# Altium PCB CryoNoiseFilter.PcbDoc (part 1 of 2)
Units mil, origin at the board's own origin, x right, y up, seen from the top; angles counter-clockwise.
Board outline 2990 x 2110 mil, 2 copper layers (Top Layer, Bottom Layer); 246 components, 223 nets, 580 pads, 66 vias.
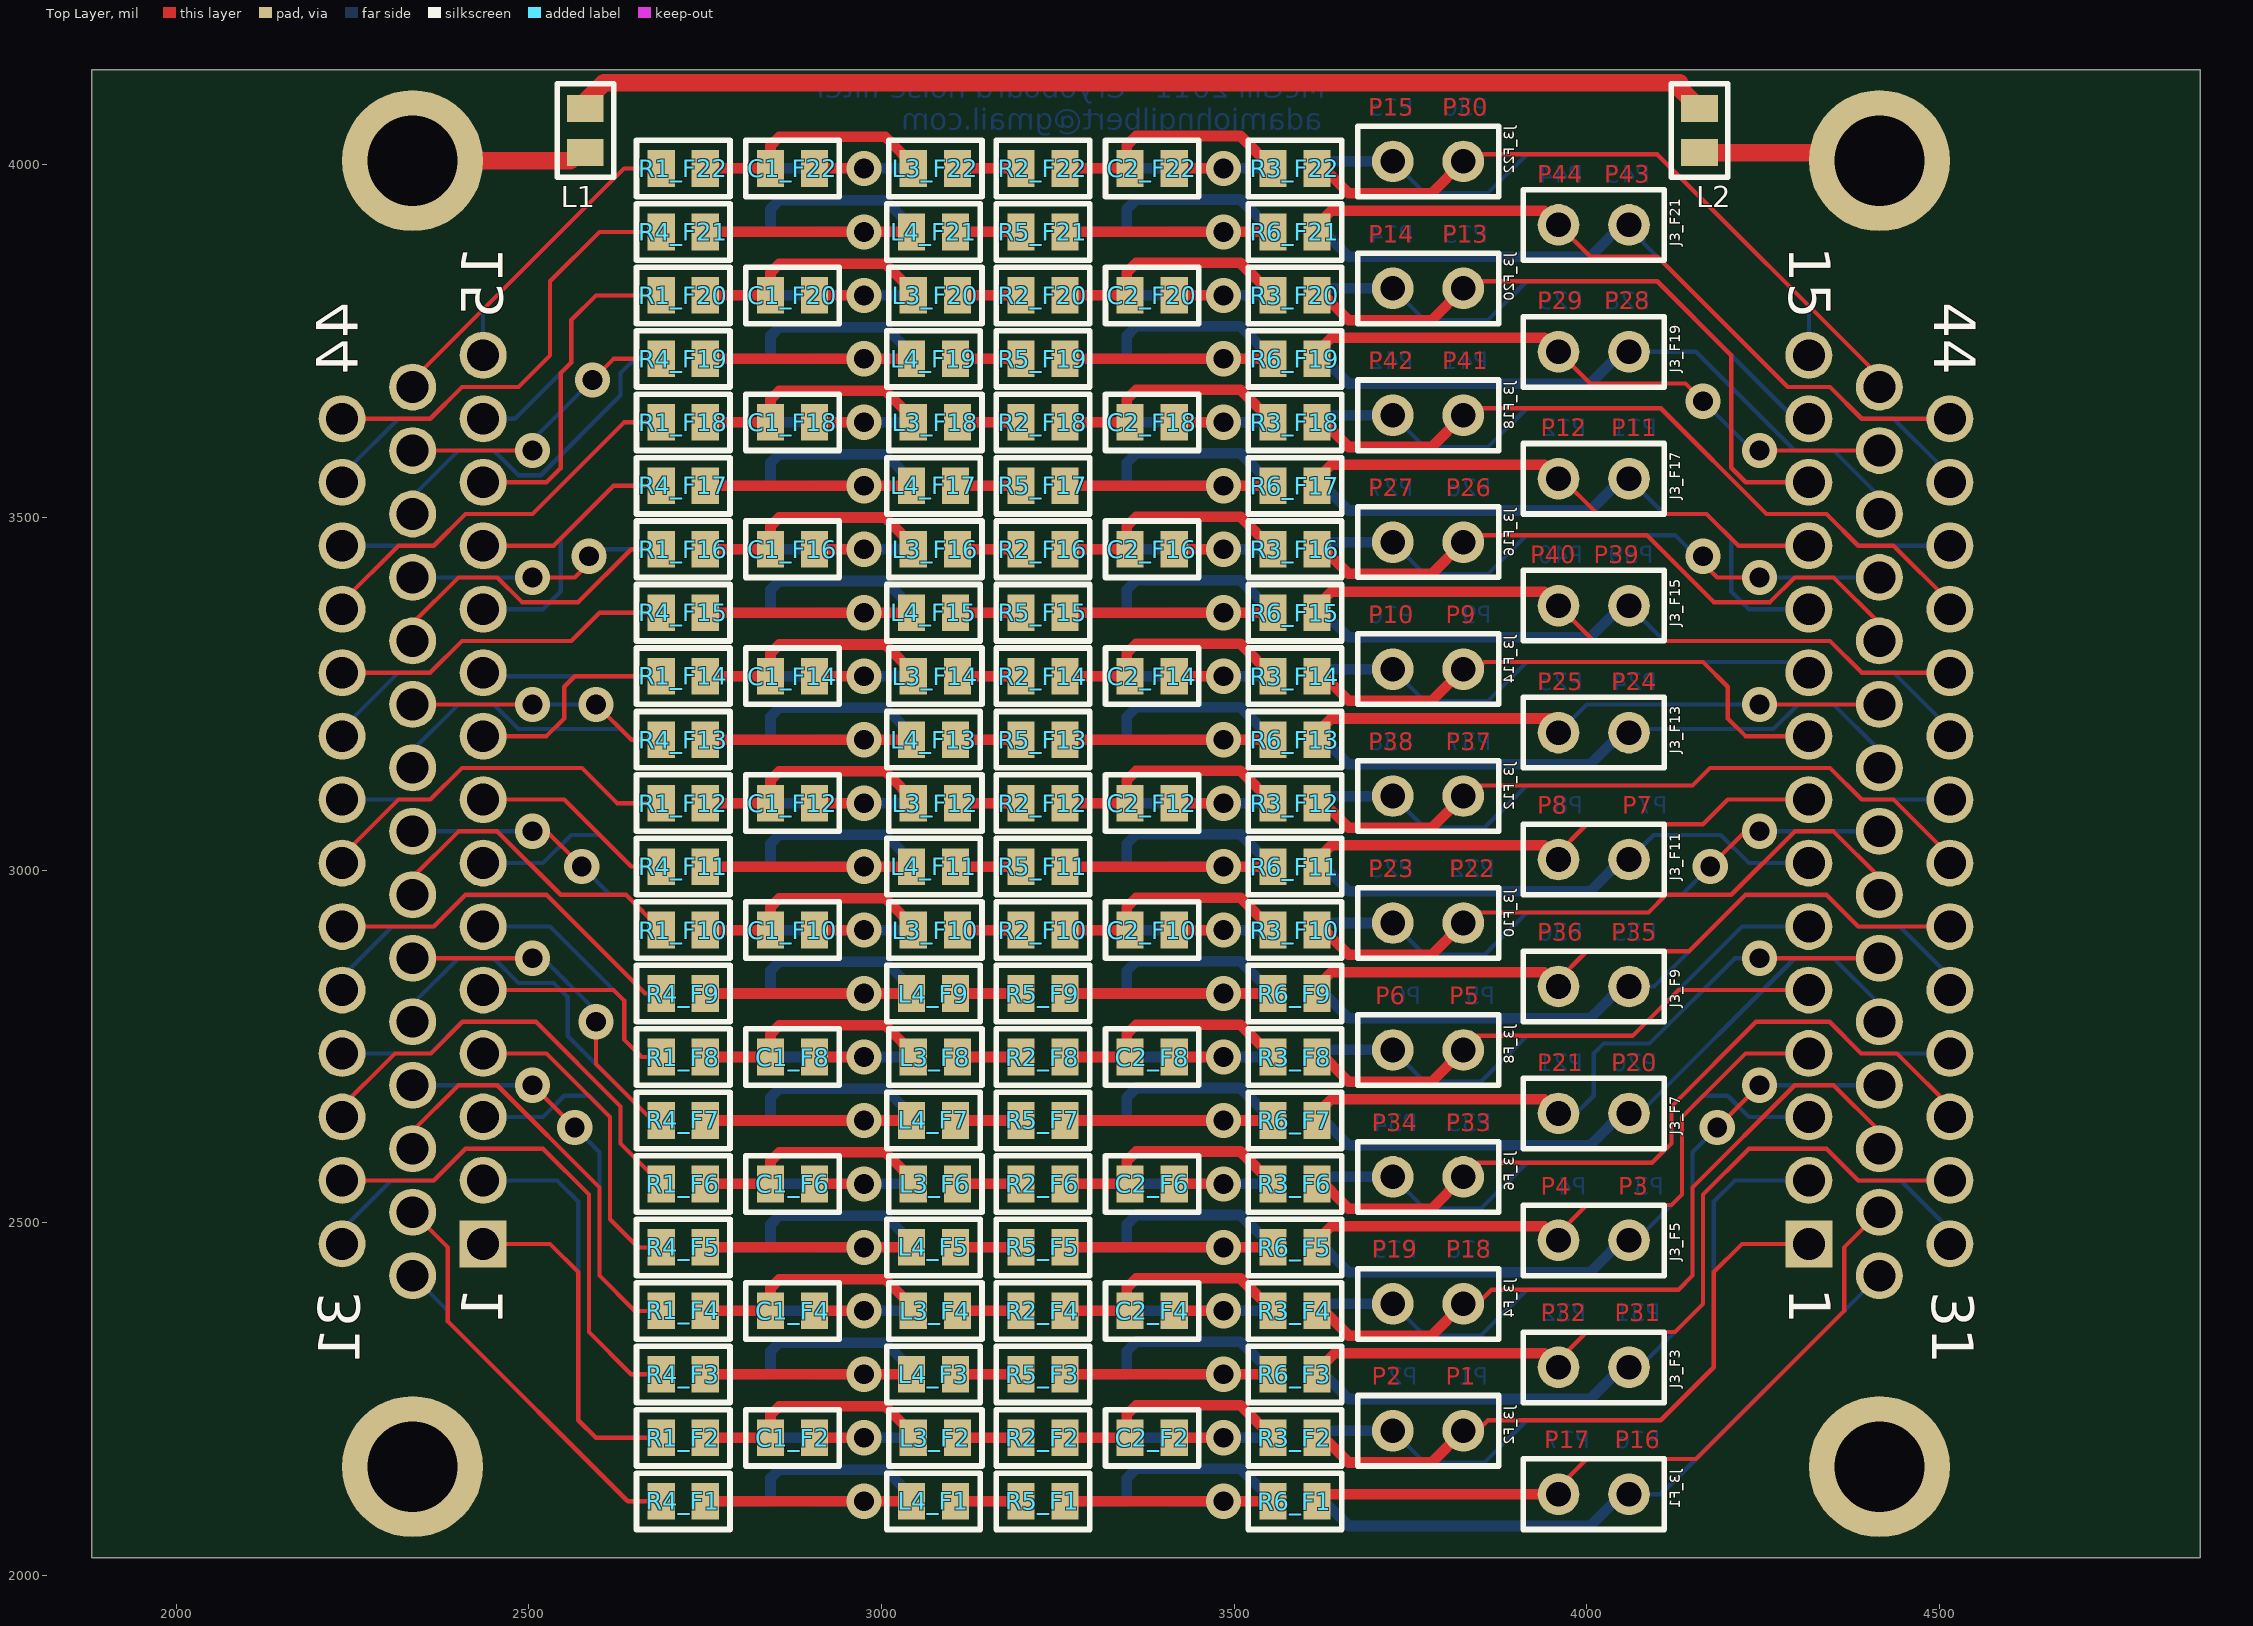
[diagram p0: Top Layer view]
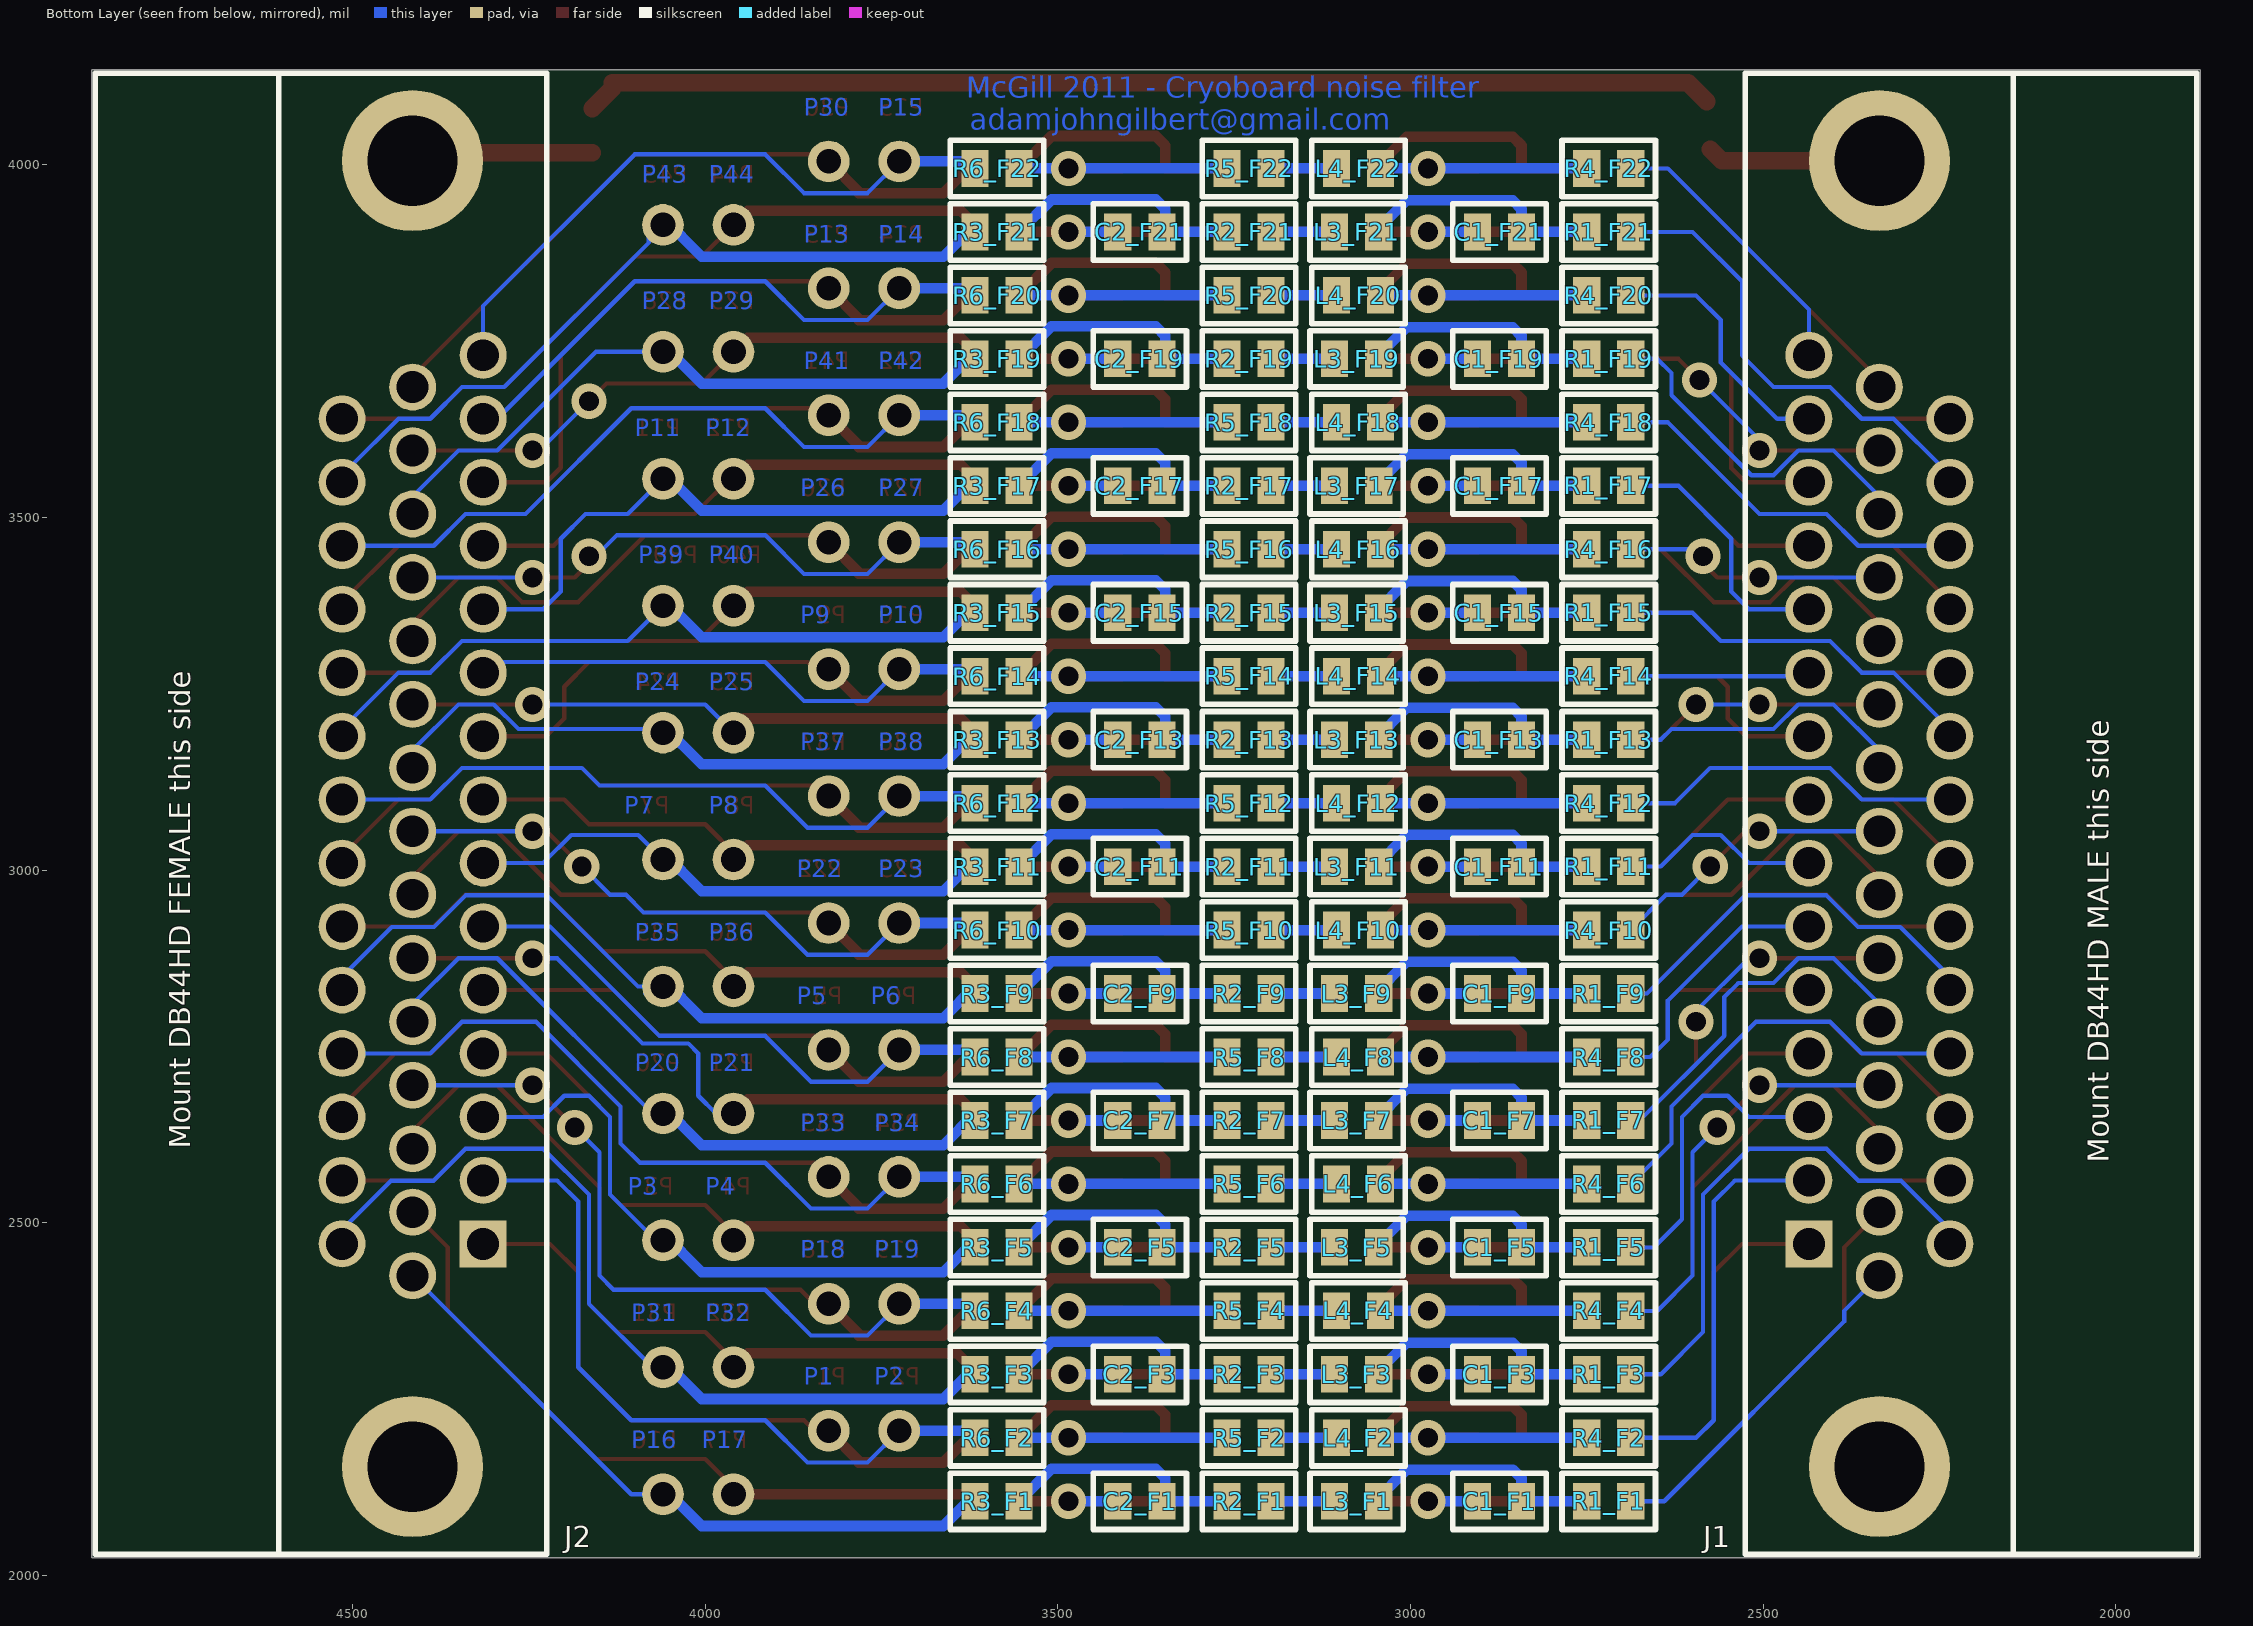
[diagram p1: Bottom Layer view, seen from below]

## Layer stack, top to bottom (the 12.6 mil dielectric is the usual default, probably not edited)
Top Layer: signal copper 1.4
Dielectric: dielectric 12.6, FR-4, Dk 4.8
Bottom Layer: signal copper 1.4

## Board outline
1885,4135 4870,4135 4870,2025 1880,2025 1880,4135

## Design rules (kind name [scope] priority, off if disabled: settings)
Clearance [All] p1: gap=5
ComponentClearance [All] p1: gap=2 collisioncheckmode=3 verticalgap=10 showdistances=FALSE
HoleToHoleClearance [All] p1: gap=5 allowstackedmicrovias=TRUE
MinimumSolderMaskSliver [All] p1: minsoldermaskwidth=0
PolygonConnect [All] p1: connectstyle=Relief reliefconductorwidth=10 reliefentries=4 polygonreliefangle="90 Angle"
RoomDefinition F21 [InComponentClass('F21')] p1: confinementstyle=ConfineIn formatcopy=TRUE lockcomponents=FALSE outline 2612.5,3860 4125,3860 4125,3970 2612.5,3970
RoomDefinition F19 [InComponentClass('F19')] p2: confinementstyle=ConfineIn formatcopy=TRUE lockcomponents=FALSE outline 2612.5,3680 4125,3680 4125,3790 2612.5,3790
RoomDefinition F17 [InComponentClass('F17')] p3: confinementstyle=ConfineIn formatcopy=TRUE lockcomponents=FALSE outline 2612.5,3500 4125,3500 4125,3610 2612.5,3610
RoomDefinition F15 [InComponentClass('F15')] p4: confinementstyle=ConfineIn formatcopy=TRUE lockcomponents=FALSE outline 2612.5,3320 4125,3320 4125,3430 2612.5,3430
RoomDefinition F13 [InComponentClass('F13')] p5: confinementstyle=ConfineIn formatcopy=TRUE lockcomponents=FALSE outline 2612.5,3140 4125,3140 4125,3250 2612.5,3250
RoomDefinition F11 [InComponentClass('F11')] p6: confinementstyle=ConfineIn formatcopy=TRUE lockcomponents=FALSE outline 2612.5,2960 4125,2960 4125,3070 2612.5,3070
RoomDefinition F9 [InComponentClass('F9')] p7: confinementstyle=ConfineIn formatcopy=TRUE lockcomponents=FALSE outline 2612.5,2780 4125,2780 4125,2890 2612.5,2890
RoomDefinition F7 [InComponentClass('F7')] p8: confinementstyle=ConfineIn formatcopy=TRUE lockcomponents=FALSE outline 2612.5,2600 4125,2600 4125,2710 2612.5,2710
RoomDefinition F5 [InComponentClass('F5')] p9: confinementstyle=ConfineIn formatcopy=TRUE lockcomponents=FALSE outline 2612.5,2420 4125,2420 4125,2530 2612.5,2530
RoomDefinition F3 [InComponentClass('F3')] p10: confinementstyle=ConfineIn formatcopy=TRUE lockcomponents=FALSE outline 2612.5,2240 4125,2240 4125,2350 2612.5,2350
RoomDefinition F22 [InComponentClass('F22')] p11: confinementstyle=ConfineIn formatcopy=FALSE lockcomponents=FALSE outline 2612.5,3950 3912.5,3950 3912.5,4060 2612.5,4060
RoomDefinition F20 [InComponentClass('F20')] p12: confinementstyle=ConfineIn formatcopy=FALSE lockcomponents=FALSE outline 2612.5,3770 3912.5,3770 3912.5,3880 2612.5,3880
RoomDefinition F18 [InComponentClass('F18')] p13: confinementstyle=ConfineIn formatcopy=FALSE lockcomponents=FALSE outline 2612.5,3590 3912.5,3590 3912.5,3700 2612.5,3700
RoomDefinition F16 [InComponentClass('F16')] p14: confinementstyle=ConfineIn formatcopy=FALSE lockcomponents=FALSE outline 2612.5,3410 3912.5,3410 3912.5,3520 2612.5,3520
RoomDefinition F14 [InComponentClass('F14')] p15: confinementstyle=ConfineIn formatcopy=FALSE lockcomponents=FALSE outline 2612.5,3230 3912.5,3230 3912.5,3340 2612.5,3340
RoomDefinition F12 [InComponentClass('F12')] p16: confinementstyle=ConfineIn formatcopy=FALSE lockcomponents=FALSE outline 2612.5,3050 3912.5,3050 3912.5,3160 2612.5,3160
RoomDefinition F10 [InComponentClass('F10')] p17: confinementstyle=ConfineIn formatcopy=FALSE lockcomponents=FALSE outline 2612.5,2870 3912.5,2870 3912.5,2980 2612.5,2980
RoomDefinition F8 [InComponentClass('F8')] p18: confinementstyle=ConfineIn formatcopy=FALSE lockcomponents=FALSE outline 2612.5,2690 3912.5,2690 3912.5,2800 2612.5,2800
RoomDefinition F6 [InComponentClass('F6')] p19: confinementstyle=ConfineIn formatcopy=FALSE lockcomponents=FALSE outline 2612.5,2510 3912.5,2510 3912.5,2620 2612.5,2620
RoomDefinition F4 [InComponentClass('F4')] p20: confinementstyle=ConfineIn formatcopy=FALSE lockcomponents=FALSE outline 2612.5,2330 3912.5,2330 3912.5,2440 2612.5,2440
RoomDefinition F2 [InComponentClass('F2')] p21: confinementstyle=ConfineIn formatcopy=FALSE lockcomponents=FALSE outline 2612.5,2150 3912.5,2150 3912.5,2260 2612.5,2260
RoomDefinition F1 [InComponentClass('F1')] p22: confinementstyle=ConfineIn formatcopy=TRUE lockcomponents=FALSE outline 2612.5,2060 4125,2060 4125,2170 2612.5,2170
RoutingVias [All] p1: holewidth=28 width=50 viastyle="Through Hole" minholewidth=28 minwidth=50 maxholewidth=28 maxwidth=50
SilkToSilkClearance [All] p1: silktosilkclearance=0
SilkscreenOverComponentPads [All] p1: minsilkscreentomaskgap=0
SolderMaskExpansion [All] p1: expansion=4
Width [All] p1: maxlimit=100 minlimit=6 preferedwidth=15
23 further rules are at their usual default settings.

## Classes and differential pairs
channel class LCFilter: F1 F2 F3 F4 F5 F6 F7 F8 F9 F10 F11 F12 F13 F14 F15 F16 F17 F18 F19 F20 F21 F22
net class OUTP[1..22]: OUTP1 OUTP2 OUTP3 OUTP4 OUTP5 OUTP6 OUTP7 OUTP8 OUTP9 OUTP10 OUTP11 OUTP12 OUTP13 OUTP14 OUTP15 OUTP16 OUTP17 OUTP18 OUTP19 OUTP20 OUTP21 OUTP22
net class OUTN[1..22]: OUTN1 OUTN2 OUTN3 OUTN4 OUTN5 OUTN6 OUTN7 OUTN8 OUTN9 OUTN10 OUTN11 OUTN12 OUTN13 OUTN14 OUTN15 OUTN16 OUTN17 OUTN18 OUTN19 OUTN20 OUTN21 OUTN22
net class INP[1..22]: INP1 INP2 INP3 INP4 INP5 INP6 INP7 INP8 INP9 INP10 INP11 INP12 INP13 INP14 INP15 INP16 INP17 INP18 INP19 INP20 INP21 INP22
net class INN[1..22]: INN1 INN2 INN3 INN4 INN5 INN6 INN7 INN8 INN9 INN10 INN11 INN12 INN13 INN14 INN15 INN16 INN17 INN18 INN19 INN20 INN21 INN22
component class F22: C1_F22 C2_F22 J3_F22 L3_F22 L4_F22 R1_F22 R2_F22 R3_F22 R4_F22 R5_F22 R6_F22
component class F21: C1_F21 C2_F21 J3_F21 L3_F21 L4_F21 R1_F21 R2_F21 R3_F21 R4_F21 R5_F21 R6_F21
component class F20: C1_F20 C2_F20 J3_F20 L3_F20 L4_F20 R1_F20 R2_F20 R3_F20 R4_F20 R5_F20 R6_F20
component class F19: C1_F19 C2_F19 J3_F19 L3_F19 L4_F19 R1_F19 R2_F19 R3_F19 R4_F19 R5_F19 R6_F19
component class F18: C1_F18 C2_F18 J3_F18 L3_F18 L4_F18 R1_F18 R2_F18 R3_F18 R4_F18 R5_F18 R6_F18
component class F17: C1_F17 C2_F17 J3_F17 L3_F17 L4_F17 R1_F17 R2_F17 R3_F17 R4_F17 R5_F17 R6_F17
component class F16: C1_F16 C2_F16 J3_F16 L3_F16 L4_F16 R1_F16 R2_F16 R3_F16 R4_F16 R5_F16 R6_F16
component class F15: C1_F15 C2_F15 J3_F15 L3_F15 L4_F15 R1_F15 R2_F15 R3_F15 R4_F15 R5_F15 R6_F15
component class F14: C1_F14 C2_F14 J3_F14 L3_F14 L4_F14 R1_F14 R2_F14 R3_F14 R4_F14 R5_F14 R6_F14
component class F13: C1_F13 C2_F13 J3_F13 L3_F13 L4_F13 R1_F13 R2_F13 R3_F13 R4_F13 R5_F13 R6_F13
component class F12: C1_F12 C2_F12 J3_F12 L3_F12 L4_F12 R1_F12 R2_F12 R3_F12 R4_F12 R5_F12 R6_F12
component class F11: C1_F11 C2_F11 J3_F11 L3_F11 L4_F11 R1_F11 R2_F11 R3_F11 R4_F11 R5_F11 R6_F11
component class F10: C1_F10 C2_F10 J3_F10 L3_F10 L4_F10 R1_F10 R2_F10 R3_F10 R4_F10 R5_F10 R6_F10
component class F9: C1_F9 C2_F9 J3_F9 L3_F9 L4_F9 R1_F9 R2_F9 R3_F9 R4_F9 R5_F9 R6_F9
component class F8: C1_F8 C2_F8 J3_F8 L3_F8 L4_F8 R1_F8 R2_F8 R3_F8 R4_F8 R5_F8 R6_F8
component class F7: C1_F7 C2_F7 J3_F7 L3_F7 L4_F7 R1_F7 R2_F7 R3_F7 R4_F7 R5_F7 R6_F7
component class F6: C1_F6 C2_F6 J3_F6 L3_F6 L4_F6 R1_F6 R2_F6 R3_F6 R4_F6 R5_F6 R6_F6
component class F5: C1_F5 C2_F5 J3_F5 L3_F5 L4_F5 R1_F5 R2_F5 R3_F5 R4_F5 R5_F5 R6_F5
component class F4: C1_F4 C2_F4 J3_F4 L3_F4 L4_F4 R1_F4 R2_F4 R3_F4 R4_F4 R5_F4 R6_F4
component class F3: C1_F3 C2_F3 J3_F3 L3_F3 L4_F3 R1_F3 R2_F3 R3_F3 R4_F3 R5_F3 R6_F3
component class F2: C1_F2 C2_F2 J3_F2 L3_F2 L4_F2 R1_F2 R2_F2 R3_F2 R4_F2 R5_F2 R6_F2
component class F1: C1_F1 C2_F1 J3_F1 L3_F1 L4_F1 R1_F1 R2_F1 R3_F1 R4_F1 R5_F1 R6_F1
component class CryoNoiseFilter: J1 J2 L1

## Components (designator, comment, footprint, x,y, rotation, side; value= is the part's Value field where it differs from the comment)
C1_F1 "0.1uF" 0805 2905,2105 r180 bottom (schematic designator C1)
C1_F2 "0.1uF" 0805 2905,2195 r180 top (schematic designator C1)
C1_F3 "0.1uF" 0805 2905,2285 r180 bottom (schematic designator C1)
C1_F4 "0.1uF" 0805 2905,2375 r180 top (schematic designator C1)
C1_F5 "0.1uF" 0805 2905,2465 r180 bottom (schematic designator C1)
C1_F6 "0.1uF" 0805 2905,2555 r180 top (schematic designator C1)
C1_F7 "0.1uF" 0805 2905,2645 r180 bottom (schematic designator C1)
C1_F8 "0.1uF" 0805 2905,2735 r180 top (schematic designator C1)
C1_F9 "0.1uF" 0805 2905,2825 r180 bottom (schematic designator C1)
C1_F10 "0.1uF" 0805 2905,2915 r180 top (schematic designator C1)
C1_F11 "0.1uF" 0805 2905,3005 r180 bottom (schematic designator C1)
C1_F12 "0.1uF" 0805 2905,3095 r180 top (schematic designator C1)
C1_F13 "0.1uF" 0805 2905,3185 r180 bottom (schematic designator C1)
C1_F14 "0.1uF" 0805 2905,3275 r180 top (schematic designator C1)
C1_F15 "0.1uF" 0805 2905,3365 r180 bottom (schematic designator C1)
C1_F16 "0.1uF" 0805 2905,3455 r180 top (schematic designator C1)
C1_F17 "0.1uF" 0805 2905,3545 r180 bottom (schematic designator C1)
C1_F18 "0.1uF" 0805 2905,3635 r180 top (schematic designator C1)
C1_F19 "0.1uF" 0805 2905,3725 r180 bottom (schematic designator C1)
C1_F20 "0.1uF" 0805 2905,3815 r180 top (schematic designator C1)
C1_F21 "0.1uF" 0805 2905,3905 r180 bottom (schematic designator C1)
C1_F22 "0.1uF" 0805 2905,3995 r180 top (schematic designator C1)
C2_F1 "0.1uF" 0805 3415,2105 r180 bottom (schematic designator C2)
C2_F2 "0.1uF" 0805 3415,2195 r180 top (schematic designator C2)
C2_F3 "0.1uF" 0805 3415,2285 r180 bottom (schematic designator C2)
C2_F4 "0.1uF" 0805 3415,2375 r180 top (schematic designator C2)
C2_F5 "0.1uF" 0805 3415,2465 r180 bottom (schematic designator C2)
C2_F6 "0.1uF" 0805 3415,2555 r180 top (schematic designator C2)
C2_F7 "0.1uF" 0805 3415,2645 r180 bottom (schematic designator C2)
C2_F8 "0.1uF" 0805 3415,2735 r180 top (schematic designator C2)
C2_F9 "0.1uF" 0805 3415,2825 r180 bottom (schematic designator C2)
C2_F10 "0.1uF" 0805 3415,2915 r180 top (schematic designator C2)
C2_F11 "0.1uF" 0805 3415,3005 r180 bottom (schematic designator C2)
C2_F12 "0.1uF" 0805 3415,3095 r180 top (schematic designator C2)
C2_F13 "0.1uF" 0805 3415,3185 r180 bottom (schematic designator C2)
C2_F14 "0.1uF" 0805 3415,3275 r180 top (schematic designator C2)
C2_F15 "0.1uF" 0805 3415,3365 r180 bottom (schematic designator C2)
C2_F16 "0.1uF" 0805 3415,3455 r180 top (schematic designator C2)
C2_F17 "0.1uF" 0805 3415,3545 r180 bottom (schematic designator C2)
C2_F18 "0.1uF" 0805 3415,3635 r180 top (schematic designator C2)
C2_F19 "0.1uF" 0805 3415,3725 r180 bottom (schematic designator C2)
C2_F20 "0.1uF" 0805 3415,3815 r180 top (schematic designator C2)
C2_F21 "0.1uF" 0805 3415,3905 r180 bottom (schematic designator C2)
C2_F22 "0.1uF" 0805 3415,3995 r180 top (schematic designator C2)
J1 "HDDB44-F, 5748482-5" DSUBHD44#1 2435,2470 r90 bottom
J2 "HDDB44-F, 5748482-5" DSUBHD44#2 4315,2470 r90 bottom
J3_F1 "Header 2pin 0.1\"" HDR1X2 4060,2115 r180 top (schematic designator J3)
J3_F2 "Header 2pin 0.1\"" HDR1X2 3825,2205 r180 top (schematic designator J3)
J3_F3 "Header 2pin 0.1\"" HDR1X2 4060,2295 r180 top (schematic designator J3)
J3_F4 "Header 2pin 0.1\"" HDR1X2 3825,2385 r180 top (schematic designator J3)
J3_F5 "Header 2pin 0.1\"" HDR1X2 4060,2475 r180 top (schematic designator J3)
J3_F6 "Header 2pin 0.1\"" HDR1X2 3825,2565 r180 top (schematic designator J3)
J3_F7 "Header 2pin 0.1\"" HDR1X2 4060,2655 r180 top (schematic designator J3)
J3_F8 "Header 2pin 0.1\"" HDR1X2 3825,2745 r180 top (schematic designator J3)
J3_F9 "Header 2pin 0.1\"" HDR1X2 4060,2835 r180 top (schematic designator J3)
J3_F10 "Header 2pin 0.1\"" HDR1X2 3825,2925 r180 top (schematic designator J3)
J3_F11 "Header 2pin 0.1\"" HDR1X2 4060,3015 r180 top (schematic designator J3)
J3_F12 "Header 2pin 0.1\"" HDR1X2 3825,3105 r180 top (schematic designator J3)
J3_F13 "Header 2pin 0.1\"" HDR1X2 4060,3195 r180 top (schematic designator J3)
J3_F14 "Header 2pin 0.1\"" HDR1X2 3825,3285 r180 top (schematic designator J3)
J3_F15 "Header 2pin 0.1\"" HDR1X2 4060,3375 r180 top (schematic designator J3)
J3_F16 "Header 2pin 0.1\"" HDR1X2 3825,3465 r180 top (schematic designator J3)
J3_F17 "Header 2pin 0.1\"" HDR1X2 4060,3555 r180 top (schematic designator J3)
J3_F18 "Header 2pin 0.1\"" HDR1X2 3825,3645 r180 top (schematic designator J3)
J3_F19 "Header 2pin 0.1\"" HDR1X2 4060,3735 r180 top (schematic designator J3)
J3_F20 "Header 2pin 0.1\"" HDR1X2 3825,3825 r180 top (schematic designator J3)
J3_F21 "Header 2pin 0.1\"" HDR1X2 4060,3915 r180 top (schematic designator J3)
J3_F22 "Header 2pin 0.1\"" HDR1X2 3825,4005 r180 top (schematic designator J3)
L1 "10uH" 0805 2580,4080 r270 top
L2 "10uH" 0805 4160,4080 r270 top
L3_F1 "10uH" 0805 3045,2105 r0 bottom (schematic designator L3)
L3_F2 "10uH" 0805 3045,2195 r0 top (schematic designator L3)
L3_F3 "10uH" 0805 3045,2285 r0 bottom (schematic designator L3)
L3_F4 "10uH" 0805 3045,2375 r0 top (schematic designator L3)
L3_F5 "10uH" 0805 3045,2465 r0 bottom (schematic designator L3)
L3_F6 "10uH" 0805 3045,2555 r0 top (schematic designator L3)
L3_F7 "10uH" 0805 3045,2645 r0 bottom (schematic designator L3)
L3_F8 "10uH" 0805 3045,2735 r0 top (schematic designator L3)
L3_F9 "10uH" 0805 3045,2825 r0 bottom (schematic designator L3)
L3_F10 "10uH" 0805 3045,2915 r0 top (schematic designator L3)
L3_F11 "10uH" 0805 3045,3005 r0 bottom (schematic designator L3)
L3_F12 "10uH" 0805 3045,3095 r0 top (schematic designator L3)
L3_F13 "10uH" 0805 3045,3185 r0 bottom (schematic designator L3)
L3_F14 "10uH" 0805 3045,3275 r0 top (schematic designator L3)
L3_F15 "10uH" 0805 3045,3365 r0 bottom (schematic designator L3)
L3_F16 "10uH" 0805 3045,3455 r0 top (schematic designator L3)
L3_F17 "10uH" 0805 3045,3545 r0 bottom (schematic designator L3)
L3_F18 "10uH" 0805 3045,3635 r0 top (schematic designator L3)
L3_F19 "10uH" 0805 3045,3725 r0 bottom (schematic designator L3)
L3_F20 "10uH" 0805 3045,3815 r0 top (schematic designator L3)
L3_F21 "10uH" 0805 3045,3905 r0 bottom (schematic designator L3)
L3_F22 "10uH" 0805 3045,3995 r0 top (schematic designator L3)
L4_F1 "10uH" 0805 3042.5,2105 r0 top (schematic designator L4)
L4_F2 "10uH" 0805 3042.5,2195 r0 bottom (schematic designator L4)
L4_F3 "10uH" 0805 3042.5,2285 r0 top (schematic designator L4)
L4_F4 "10uH" 0805 3042.5,2375 r0 bottom (schematic designator L4)
L4_F5 "10uH" 0805 3042.5,2465 r0 top (schematic designator L4)
L4_F6 "10uH" 0805 3042.5,2555 r0 bottom (schematic designator L4)
L4_F7 "10uH" 0805 3042.5,2645 r0 top (schematic designator L4)
L4_F8 "10uH" 0805 3042.5,2735 r0 bottom (schematic designator L4)
L4_F9 "10uH" 0805 3042.5,2825 r0 top (schematic designator L4)
L4_F10 "10uH" 0805 3042.5,2915 r0 bottom (schematic designator L4)
L4_F11 "10uH" 0805 3042.5,3005 r0 top (schematic designator L4)
L4_F12 "10uH" 0805 3042.5,3095 r0 bottom (schematic designator L4)
L4_F13 "10uH" 0805 3042.5,3185 r0 top (schematic designator L4)
L4_F14 "10uH" 0805 3042.5,3275 r0 bottom (schematic designator L4)
L4_F15 "10uH" 0805 3042.5,3365 r0 top (schematic designator L4)
L4_F16 "10uH" 0805 3042.5,3455 r0 bottom (schematic designator L4)
L4_F17 "10uH" 0805 3042.5,3545 r0 top (schematic designator L4)
L4_F18 "10uH" 0805 3042.5,3635 r0 bottom (schematic designator L4)
L4_F19 "10uH" 0805 3042.5,3725 r0 top (schematic designator L4)
L4_F20 "10uH" 0805 3042.5,3815 r0 bottom (schematic designator L4)
L4_F21 "10uH" 0805 3042.5,3905 r0 top (schematic designator L4)
L4_F22 "10uH" 0805 3042.5,3995 r0 bottom (schematic designator L4)
R1_F1 "0805" 0805 2687.5,2105 r0 bottom (schematic designator R1)
R1_F2 "0805" 0805 2687.5,2195 r0 top (schematic designator R1)
R1_F3 "0805" 0805 2687.5,2285 r0 bottom (schematic designator R1)
R1_F4 "0805" 0805 2687.5,2375 r0 top (schematic designator R1)
R1_F5 "0805" 0805 2687.5,2465 r0 bottom (schematic designator R1)
R1_F6 "0805" 0805 2687.5,2555 r0 top (schematic designator R1)
R1_F7 "0805" 0805 2687.5,2645 r0 bottom (schematic designator R1)
R1_F8 "0805" 0805 2687.5,2735 r0 top (schematic designator R1)
R1_F9 "0805" 0805 2687.5,2825 r0 bottom (schematic designator R1)
R1_F10 "0805" 0805 2687.5,2915 r0 top (schematic designator R1)
R1_F11 "0805" 0805 2687.5,3005 r0 bottom (schematic designator R1)
R1_F12 "0805" 0805 2687.5,3095 r0 top (schematic designator R1)
R1_F13 "0805" 0805 2687.5,3185 r0 bottom (schematic designator R1)
R1_F14 "0805" 0805 2687.5,3275 r0 top (schematic designator R1)
R1_F15 "0805" 0805 2687.5,3365 r0 bottom (schematic designator R1)
R1_F16 "0805" 0805 2687.5,3455 r0 top (schematic designator R1)
R1_F17 "0805" 0805 2687.5,3545 r0 bottom (schematic designator R1)
R1_F18 "0805" 0805 2687.5,3635 r0 top (schematic designator R1)
R1_F19 "0805" 0805 2687.5,3725 r0 bottom (schematic designator R1)
R1_F20 "0805" 0805 2687.5,3815 r0 top (schematic designator R1)
R1_F21 "0805" 0805 2687.5,3905 r0 bottom (schematic designator R1)
R1_F22 "0805" 0805 2687.5,3995 r0 top (schematic designator R1)
R2_F1 "0805" 0805 3197.5,2105 r0 bottom (schematic designator R2)
R2_F2 "0805" 0805 3197.5,2195 r0 top (schematic designator R2)
R2_F3 "0805" 0805 3197.5,2285 r0 bottom (schematic designator R2)
R2_F4 "0805" 0805 3197.5,2375 r0 top (schematic designator R2)
R2_F5 "0805" 0805 3197.5,2465 r0 bottom (schematic designator R2)
R2_F6 "0805" 0805 3197.5,2555 r0 top (schematic designator R2)
R2_F7 "0805" 0805 3197.5,2645 r0 bottom (schematic designator R2)
R2_F8 "0805" 0805 3197.5,2735 r0 top (schematic designator R2)
R2_F9 "0805" 0805 3197.5,2825 r0 bottom (schematic designator R2)
R2_F10 "0805" 0805 3197.5,2915 r0 top (schematic designator R2)
R2_F11 "0805" 0805 3197.5,3005 r0 bottom (schematic designator R2)
R2_F12 "0805" 0805 3197.5,3095 r0 top (schematic designator R2)
R2_F13 "0805" 0805 3197.5,3185 r0 bottom (schematic designator R2)
R2_F14 "0805" 0805 3197.5,3275 r0 top (schematic designator R2)
R2_F15 "0805" 0805 3197.5,3365 r0 bottom (schematic designator R2)
R2_F16 "0805" 0805 3197.5,3455 r0 top (schematic designator R2)
R2_F17 "0805" 0805 3197.5,3545 r0 bottom (schematic designator R2)
R2_F18 "0805" 0805 3197.5,3635 r0 top (schematic designator R2)
R2_F19 "0805" 0805 3197.5,3725 r0 bottom (schematic designator R2)
R2_F20 "0805" 0805 3197.5,3815 r0 top (schematic designator R2)
R2_F21 "0805" 0805 3197.5,3905 r0 bottom (schematic designator R2)
R2_F22 "0805" 0805 3197.5,3995 r0 top (schematic designator R2)
R3_F1 "0805" 0805 3555,2105 r0 bottom (schematic designator R3)
R3_F2 "0805" 0805 3555,2195 r0 top (schematic designator R3)
R3_F3 "0805" 0805 3555,2285 r0 bottom (schematic designator R3)
R3_F4 "0805" 0805 3555,2375 r0 top (schematic designator R3)
R3_F5 "0805" 0805 3555,2465 r0 bottom (schematic designator R3)
R3_F6 "0805" 0805 3555,2555 r0 top (schematic designator R3)
R3_F7 "0805" 0805 3555,2645 r0 bottom (schematic designator R3)
R3_F8 "0805" 0805 3555,2735 r0 top (schematic designator R3)
R3_F9 "0805" 0805 3555,2825 r0 bottom (schematic designator R3)
R3_F10 "0805" 0805 3555,2915 r0 top (schematic designator R3)
R3_F11 "0805" 0805 3555,3005 r0 bottom (schematic designator R3)
R3_F12 "0805" 0805 3555,3095 r0 top (schematic designator R3)
R3_F13 "0805" 0805 3555,3185 r0 bottom (schematic designator R3)
R3_F14 "0805" 0805 3555,3275 r0 top (schematic designator R3)
R3_F15 "0805" 0805 3555,3365 r0 bottom (schematic designator R3)
R3_F16 "0805" 0805 3555,3455 r0 top (schematic designator R3)
R3_F17 "0805" 0805 3555,3545 r0 bottom (schematic designator R3)
R3_F18 "0805" 0805 3555,3635 r0 top (schematic designator R3)
R3_F19 "0805" 0805 3555,3725 r0 bottom (schematic designator R3)
R3_F20 "0805" 0805 3555,3815 r0 top (schematic designator R3)
R3_F21 "0805" 0805 3555,3905 r0 bottom (schematic designator R3)
R3_F22 "0805" 0805 3555,3995 r0 top (schematic designator R3)
R4_F1 "0805" 0805 2687.5,2105 r0 top (schematic designator R4)
R4_F2 "0805" 0805 2687.5,2195 r0 bottom (schematic designator R4)
R4_F3 "0805" 0805 2687.5,2285 r0 top (schematic designator R4)
R4_F4 "0805" 0805 2687.5,2375 r0 bottom (schematic designator R4)
R4_F5 "0805" 0805 2687.5,2465 r0 top (schematic designator R4)
R4_F6 "0805" 0805 2687.5,2555 r0 bottom (schematic designator R4)
R4_F7 "0805" 0805 2687.5,2645 r0 top (schematic designator R4)
R4_F8 "0805" 0805 2687.5,2735 r0 bottom (schematic designator R4)
R4_F9 "0805" 0805 2687.5,2825 r0 top (schematic designator R4)
R4_F10 "0805" 0805 2687.5,2915 r0 bottom (schematic designator R4)
R4_F11 "0805" 0805 2687.5,3005 r0 top (schematic designator R4)
R4_F12 "0805" 0805 2687.5,3095 r0 bottom (schematic designator R4)
R4_F13 "0805" 0805 2687.5,3185 r0 top (schematic designator R4)
R4_F14 "0805" 0805 2687.5,3275 r0 bottom (schematic designator R4)
R4_F15 "0805" 0805 2687.5,3365 r0 top (schematic designator R4)
R4_F16 "0805" 0805 2687.5,3455 r0 bottom (schematic designator R4)
R4_F17 "0805" 0805 2687.5,3545 r0 top (schematic designator R4)
R4_F18 "0805" 0805 2687.5,3635 r0 bottom (schematic designator R4)
R4_F19 "0805" 0805 2687.5,3725 r0 top (schematic designator R4)
R4_F20 "0805" 0805 2687.5,3815 r0 bottom (schematic designator R4)
R4_F21 "0805" 0805 2687.5,3905 r0 top (schematic designator R4)
R4_F22 "0805" 0805 2687.5,3995 r0 bottom (schematic designator R4)
R5_F1 "0805" 0805 3197.5,2105 r0 top (schematic designator R5)
R5_F2 "0805" 0805 3197.5,2195 r0 bottom (schematic designator R5)
R5_F3 "0805" 0805 3197.5,2285 r0 top (schematic designator R5)
R5_F4 "0805" 0805 3197.5,2375 r0 bottom (schematic designator R5)
R5_F5 "0805" 0805 3197.5,2465 r0 top (schematic designator R5)
R5_F6 "0805" 0805 3197.5,2555 r0 bottom (schematic designator R5)
R5_F7 "0805" 0805 3197.5,2645 r0 top (schematic designator R5)
R5_F8 "0805" 0805 3197.5,2735 r0 bottom (schematic designator R5)
R5_F9 "0805" 0805 3197.5,2825 r0 top (schematic designator R5)
R5_F10 "0805" 0805 3197.5,2915 r0 bottom (schematic designator R5)
R5_F11 "0805" 0805 3197.5,3005 r0 top (schematic designator R5)
R5_F12 "0805" 0805 3197.5,3095 r0 bottom (schematic designator R5)
R5_F13 "0805" 0805 3197.5,3185 r0 top (schematic designator R5)
R5_F14 "0805" 0805 3197.5,3275 r0 bottom (schematic designator R5)
R5_F15 "0805" 0805 3197.5,3365 r0 top (schematic designator R5)
R5_F16 "0805" 0805 3197.5,3455 r0 bottom (schematic designator R5)
R5_F17 "0805" 0805 3197.5,3545 r0 top (schematic designator R5)
R5_F18 "0805" 0805 3197.5,3635 r0 bottom (schematic designator R5)
R5_F19 "0805" 0805 3197.5,3725 r0 top (schematic designator R5)
R5_F20 "0805" 0805 3197.5,3815 r0 bottom (schematic designator R5)
R5_F21 "0805" 0805 3197.5,3905 r0 top (schematic designator R5)
R5_F22 "0805" 0805 3197.5,3995 r0 bottom (schematic designator R5)
R6_F1 "0805" 0805 3555,2105 r0 top (schematic designator R6)
R6_F2 "0805" 0805 3555,2195 r0 bottom (schematic designator R6)
R6_F3 "0805" 0805 3555,2285 r0 top (schematic designator R6)
R6_F4 "0805" 0805 3555,2375 r0 bottom (schematic designator R6)
R6_F5 "0805" 0805 3555,2465 r0 top (schematic designator R6)
R6_F6 "0805" 0805 3555,2555 r0 bottom (schematic designator R6)
R6_F7 "0805" 0805 3555,2645 r0 top (schematic designator R6)
R6_F8 "0805" 0805 3555,2735 r0 bottom (schematic designator R6)
R6_F9 "0805" 0805 3555,2825 r0 top (schematic designator R6)
R6_F10 "0805" 0805 3555,2915 r0 bottom (schematic designator R6)
R6_F11 "0805" 0805 3555,3005 r0 top (schematic designator R6)
R6_F12 "0805" 0805 3555,3095 r0 bottom (schematic designator R6)
R6_F13 "0805" 0805 3555,3185 r0 top (schematic designator R6)
R6_F14 "0805" 0805 3555,3275 r0 bottom (schematic designator R6)
R6_F15 "0805" 0805 3555,3365 r0 top (schematic designator R6)
R6_F16 "0805" 0805 3555,3455 r0 bottom (schematic designator R6)
R6_F17 "0805" 0805 3555,3545 r0 top (schematic designator R6)
R6_F18 "0805" 0805 3555,3635 r0 bottom (schematic designator R6)
R6_F19 "0805" 0805 3555,3725 r0 top (schematic designator R6)
R6_F20 "0805" 0805 3555,3815 r0 bottom (schematic designator R6)
R6_F21 "0805" 0805 3555,3905 r0 top (schematic designator R6)
R6_F22 "0805" 0805 3555,3995 r0 bottom (schematic designator R6)

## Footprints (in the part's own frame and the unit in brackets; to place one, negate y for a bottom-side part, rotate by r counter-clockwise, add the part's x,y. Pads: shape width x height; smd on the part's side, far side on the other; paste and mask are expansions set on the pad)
0805 [mil]
  rect 38.5x52 smd: 1(0,0) 2(62.5,0)
  silkscreen extent -35,-40 98,40
DSUBHD44#1 [mm]
  rect 1.69x1.69 hole 1.143: 1(0,0)
  round 1.69 hole 1.143: 2(2.286,0) 3(4.572,0) 4(6.858,0) 5(9.144,0) 6(11.43,0) 7(13.716,0) 8(16.002,0) 9(18.288,0) 10(20.574,0) 11(22.86,0) 12(25.146,0) 13(27.432,0) 14(29.718,0) 15(32.004,0) 16(-1.143,-2.54) 17(1.143,-2.54) 18(3.429,-2.54) 19(5.715,-2.54) 20(8.001,-2.54) 21(10.287,-2.54) 22(12.573,-2.54) 23(14.859,-2.54) 24(17.145,-2.54) 25(19.431,-2.54) 26(21.717,-2.54) 27(24.003,-2.54) 28(26.289,-2.54) 29(28.575,-2.54) 30(30.861,-2.54) 31(0,-5.08) 32(2.286,-5.08) 33(4.572,-5.08) 34(6.858,-5.08) 35(9.144,-5.08) 36(11.43,-5.08) 37(13.716,-5.08) 38(16.002,-5.08) 39(18.288,-5.08) 40(20.574,-5.08) 41(22.86,-5.08) 42(25.146,-5.08) 43(27.432,-5.08) 44(29.718,-5.08)
  round 5.08 hole 3.251: 45(-8.026,-2.54) 46(39.014,-2.54)
  silkscreen extent -11.18,-13.97 42.16,2.29
DSUBHD44#2 [mm]
  rect 1.69x1.69 hole 1.143: 1(0,0)
  round 1.69 hole 1.143: 2(2.286,0) 3(4.572,0) 4(6.858,0) 5(9.144,0) 6(11.43,0) 7(13.716,0) 8(16.002,0) 9(18.288,0) 10(20.574,0) 11(22.86,0) 12(25.146,0) 13(27.432,0) 14(29.718,0) 15(32.004,0) 16(-1.143,2.54) 17(1.143,2.54) 18(3.429,2.54) 19(5.715,2.54) 20(8.001,2.54) 21(10.287,2.54) 22(12.573,2.54) 23(14.859,2.54) 24(17.145,2.54) 25(19.431,2.54) 26(21.717,2.54) 27(24.003,2.54) 28(26.289,2.54) 29(28.575,2.54) 30(30.861,2.54) 31(0,5.08) 32(2.286,5.08) 33(4.572,5.08) 34(6.858,5.08) 35(9.144,5.08) 36(11.43,5.08) 37(13.716,5.08) 38(16.002,5.08) 39(18.288,5.08) 40(20.574,5.08) 41(22.86,5.08) 42(25.146,5.08) 43(27.432,5.08) 44(29.718,5.08)
  round 5.08 hole 3.251: 45(-8.026,2.54) 46(39.014,2.54)
  silkscreen extent -11.18,-2.29 42.16,13.97
HDR1X2 [mm]
  round 1.5 hole 0.889: 1(0,0) 2(2.54,0)
  silkscreen extent -1.27,-1.27 3.81,1.27

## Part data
C1_F1 C1_F2 C1_F3 C1_F4 C1_F5 C1_F6 C1_F7 C1_F8 C1_F9 C1_F10 C1_F11 C1_F12 C1_F13 C1_F14 C1_F15 C1_F16 C1_F17 C1_F18 C1_F19 C1_F20 C1_F21 C1_F22 C2_F1 C2_F2 C2_F3 C2_F4 C2_F5 C2_F6 C2_F7 C2_F8 C2_F9 C2_F10 C2_F11 C2_F12 C2_F13 C2_F14 C2_F15 C2_F16 C2_F17 C2_F18 C2_F19 C2_F20 C2_F21 C2_F22: library part Cap0603, "Capacitor, Ceramic, 0803"
J1 J2: library part DB44HD-F, "CONN, High Density DB44 Female"
J3_F1 J3_F2 J3_F3 J3_F4 J3_F5 J3_F6 J3_F7 J3_F8 J3_F9 J3_F10 J3_F11 J3_F12 J3_F13 J3_F14 J3_F15 J3_F16 J3_F17 J3_F18 J3_F19 J3_F20 J3_F21 J3_F22: library part Header2, "Header, 0.1\", 2-Pin straight (Any equivalent - may need to be value added)"
L1 L2 L3_F1 L3_F2 L3_F3 L3_F4 L3_F5 L3_F6 L3_F7 L3_F8 L3_F9 L3_F10 L3_F11 L3_F12 L3_F13 L3_F14 L3_F15 L3_F16 L3_F17 L3_F18 L3_F19 L3_F20 L3_F21 L3_F22 L4_F1 L4_F2 L4_F3 L4_F4 L4_F5 L4_F6 L4_F7 L4_F8 L4_F9 L4_F10 L4_F11 L4_F12 L4_F13 L4_F14 L4_F15 L4_F16 L4_F17 L4_F18 L4_F19 L4_F20 L4_F21 L4_F22: library part Inductor0, "Inductor 47uH, 5.46 Ohm, 0.1A, 0805"
R1_F1 R1_F2 R1_F3 R1_F4 R1_F5 R1_F6 R1_F7 R1_F8 R1_F9 R1_F10 R1_F11 R1_F12 R1_F13 R1_F14 R1_F15 R1_F16 R1_F17 R1_F18 R1_F19 R1_F20 R1_F21 R1_F22 R2_F1 R2_F2 R2_F3 R2_F4 R2_F5 R2_F6 R2_F7 R2_F8 R2_F9 R2_F10 R2_F11 R2_F12 R2_F13 R2_F14 R2_F15 R2_F16 R2_F17 R2_F18 R2_F19 R2_F20 R2_F21 R2_F22 R3_F1 R3_F2 R3_F3 R3_F4 R3_F5 R3_F6 R3_F7 R3_F8 R3_F9 R3_F10 R3_F11 R3_F12 R3_F13 R3_F14 R3_F15 R3_F16 R3_F17 R3_F18 R3_F19 R3_F20 R3_F21 R3_F22 R4_F1 R4_F2 R4_F3 R4_F4 R4_F5 R4_F6 R4_F7 R4_F8 R4_F9 R4_F10 R4_F11 R4_F12 R4_F13 R4_F14 R4_F15 R4_F16 R4_F17 R4_F18 R4_F19 R4_F20 R4_F21 R4_F22 R5_F1 R5_F2 R5_F3 R5_F4 R5_F5 R5_F6 R5_F7 R5_F8 R5_F9 R5_F10 R5_F11 R5_F12 R5_F13 R5_F14 R5_F15 R5_F16 R5_F17 R5_F18 R5_F19 R5_F20 R5_F21 R5_F22 R6_F1 R6_F2 R6_F3 R6_F4 R6_F5 R6_F6 R6_F7 R6_F8 R6_F9 R6_F10 R6_F11 R6_F12 R6_F13 R6_F14 R6_F15 R6_F16 R6_F17 R6_F18 R6_F19 R6_F20 R6_F21 R6_F22: library part Res0603, "Resistor"

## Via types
v1: diameter 50, hole 28, Top Layer to Bottom Layer, 66 vias

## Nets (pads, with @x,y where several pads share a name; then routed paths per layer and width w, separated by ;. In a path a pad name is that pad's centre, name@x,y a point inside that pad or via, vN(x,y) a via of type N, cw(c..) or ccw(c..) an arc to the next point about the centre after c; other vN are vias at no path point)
GND: L1.1 L2.1 | length 1610.8
  Top Layer w25: L1.1@2580,4090 2606.49,4116.49 4131.49,4116.49 4131.49,4108.51 L2.1@4160,4080
INN1: J1.17 R4_F1.1 | length 583.8
  Top Layer w6: J1.17@2335,2515 2385,2465 2385,2360 2640,2105 R4_F1.1@2687.5,2105
INN2: J1.2 R4_F2.1 | length 585.3
  Bottom Layer w6: J1.2@2435,2560 2540,2560 2570,2530 2570,2220 2595,2195 R4_F2.1@2687.5,2195
INN3: J1.32 R4_F3.1 | length 712.9
  Top Layer w6: J1.32@2240,2560 2365,2560 2410,2605 2520,2605 2585,2540 2585,2345 2645,2285 R4_F3.1@2687.5,2285
INN4: J1.19 R4_F4.1 | length 587.6
  Top Layer w6: v1(2505,2695) v1(2565,2635)
  Bottom Layer w6: J1.19@2335,2695 v1(2505,2695) ; v1(2565,2635) 2600,2600 2600,2425 2650,2375 R4_F4.1@2687.5,2375
INN5: J1.4 R4_F5.1 | length 451.3
  Top Layer w6: J1.4@2435,2740 2525,2740 2615,2650 2615,2505 2655,2465 R4_F5.1@2687.5,2465
INN6: J1.34 R4_F6.1 | length 602.2
  Bottom Layer w6: J1.34@2230,2740 J1.34@2235,2740 2360,2740 2405,2785 2510,2785 2630,2665 2630,2612.5 R4_F6.1@2687.5,2555
INN7: J1.21 R4_F7.1 | length 501.7
  Top Layer w6: J1.21@2335,2875 v1(2505,2875) ; v1@2595,2795 v1(2595,2785) 2595,2725 2675,2645 R4_F7.1@2687.5,2645
  Bottom Layer w6: v1(2505,2875) 2520,2875 2595,2800 v1(2595,2785)
INN8: J1.6 R4_F8.1 | length 361.3
  Bottom Layer w6: J1.6@2435,2920 2530,2920 2635,2815 2635,2760 2660,2735 R4_F8.1@2687.5,2735
INN9: J1.36 R4_F9.1 | length 524.1
  Top Layer w6: J1.36@2240,2920 2365,2920 2410,2965 2525,2965 2665,2825 R4_F9.1@2687.5,2825
INN10: J1.23 R4_F10.1 | length 417.6
  Top Layer w6: v1(2505,3055) 2520,3055 2520,3060 v1(2575,3005)
  Bottom Layer w6: J1.23@2335,3055 v1(2505,3055) ; v1(2575,3005) 2615,2965 2637.5,2965 R4_F10.1@2687.5,2915
INN11: J1.8 R4_F11.1 | length 291.9
  Top Layer w6: J1.8@2435,3100 2550,3100 2645,3005 R4_F11.1@2687.5,3005
INN12: J1.38 R4_F12.1 | length 496.9
  Bottom Layer w6: J1.38@2230,3100 J1.38@2235,3100 2360,3100 2405,3145 2575,3145 2625,3095 R4_F12.1@2687.5,3095
INN13: J1.25 R4_F13.1 | length 373.2
  Top Layer w6: J1.25@2335,3235 v1(2505,3235) ; v1(2595,3235) 2645,3185 R4_F13.1@2687.5,3185
  Bottom Layer w6: v1(2505,3235) v1(2595,3235)
INN14: J1.10 R4_F14.1 | length 247.5
  Bottom Layer w6: J1.10@2435,3275 R4_F14.1@2682.5,3275
INN15: J1.40 R4_F15.1 | length 487.7
  Top Layer w6: J1.40@2235,3280 2360,3280 2405,3325 2560,3325 2600,3365 R4_F15.1@2687.5,3365
INN16: J1.27 R4_F16.1 | length 389.1
  Top Layer w6: v1(2505,3415) 2565,3415 2580,3430 2580,3440 v1(2585,3445)
  Bottom Layer w6: J1.27@2335,3415 v1(2505,3415) ; v1(2585,3445) 2580,3440 2590,3440 2605,3455 R4_F16.1@2687.5,3455
INN17: J1.12 R4_F17.1 | length 287.7
  Top Layer w6: J1.12@2435,3460 2535,3460 2620,3545 R4_F17.1@2687.5,3545
INN18: J1.42 R4_F18.1 | length 525
  Bottom Layer w6: J1.42@2235,3460 2365,3460 2410,3505 2505,3505 2635,3635 R4_F18.1@2687.5,3635
INN19: J1.29 R4_F19.1 | length 446.3
  Top Layer w6: J1.29@2335,3595 v1(2505,3595) ; v1@2575,3680 2620,3725 R4_F19.1@2687.5,3725
  Bottom Layer w6: v1@2515,3595 v1(2505,3595) 2505,3610 v1(2590,3695)
INN20: J1.14 R4_F20.1 | length 360.1
  Bottom Layer w6: J1.14@2435,3640 2480,3640 2560,3720 2560,3780 2595,3815 R4_F20.1@2687.5,3815
INN21: J1.44 R4_F21.1 | length 623.8
  Top Layer w6: J1.44@2235,3640 2360,3640 2405,3685 2485,3685 2530,3730 2530,3835 2600,3905 R4_F21.1@2687.5,3905
INN22: J1.15 R4_F22.1 | length 400.3
  Bottom Layer w6: J1.15@2435,3730 2435,3795 2635,3995 R4_F22.1@2687.5,3995
INP1: J1.16 R1_F1.1 | length 508.8
  Bottom Layer w6: J1.16@2335,2440 J1.16@2335,2425 2385,2375 2385,2360 2640,2105 R1_F1.1@2687.5,2105
INP2: J1.1 R1_F2.1 | length 489.4
  Top Layer w6: J1.1@2435,2470 2530,2470 2570,2430 2570,2220 2595,2195 R1_F2.1@2687.5,2195
INP3: J1.31 R1_F3.1 | length 765.5
  Bottom Layer w6: J1.31@2239.5,2469.5 2239.5,2494.5 2304.5,2559.5 2364.5,2559.5 2410,2605 2520,2605 2585,2540 2585,2345 2645,2285 R1_F3.1@2687.5,2285
INP4: J1.18 R1_F4.1 | length 610.2
  Top Layer w6: J1.18@2335,2605 2335,2630 2400,2695 2455,2695 2600,2550 2600,2425 2650,2375 R1_F4.1@2687.5,2375
INP5: J1.3 R1_F5.1 | length 438.9
  Bottom Layer w6: J1.3@2435,2650 2520,2650 2550,2680 2585,2680 2615,2650 2615,2505 2655,2465 R1_F5.1@2687.5,2465
INP6: J1.33 R1_F6.1 | length 638.8
  Top Layer w6: J1.33@2227.5,2657.5 2310,2740 2361,2740 2406,2785 2510,2785 2630,2665 2630,2612.5 R1_F6.1@2687.5,2555
INP7: J1.20 R1_F7.1 | length 531.9
  Bottom Layer w6: J1.20@2335,2785 2335,2810 2400,2875 2450,2875 2485,2840 2535,2840 2555,2820 2555,2765 2675,2645 R1_F7.1@2687.5,2645
INP8: J1.5 R1_F8.1 | length 324.1
  Top Layer w6: J1.5@2435,2830 2620,2830 2635,2815 2635,2760 2660,2735 R1_F8.1@2687.5,2735
INP9: J1.35 R1_F9.1 | length 575.3
  Bottom Layer w6: J1.35@2240.5,2829.5 2240.5,2854.5 2305.5,2919.5 2365.5,2919.5 2410.5,2964.5 2525,2964.5 2664.5,2825 R1_F9.1@2687.5,2825
INP10: J1.22 R1_F10.1 | length 462.4
  Top Layer w6: J1.22@2335,2965 2335,2990 2400,3055 2455,3055 2545,2965 2637.5,2965 R1_F10.1@2687.5,2915
INP11: J1.7 R1_F11.1 | length 287.7
  Bottom Layer w6: J1.7@2435,3010 2520,3010 2560,3050 2600,3050 2645,3005 R1_F11.1@2687.5,3005
INP12: J1.37 R1_F12.1 | length 535
  Top Layer w6: J1.37@2235,3010 2235,3020 2315,3100 2360,3100 2405,3145 2575,3145 2625,3095 R1_F12.1@2687.5,3095
INP13: J1.24 R1_F13.1 | length 425.1
  Bottom Layer w6: J1.24@2335,3145 2335,3170 2400,3235 2450,3235 2485,3200 2630,3200 2645,3185 R1_F13.1@2687.5,3185
INP14: J1.9 R1_F14.1 | length 314.1
  Top Layer w6: J1.9@2435,3190 2525,3190 2550,3215 2550,3260 2565,3275 R1_F14.1@2687.5,3275
INP15: J1.39 R1_F15.1 | length 530.8
  Bottom Layer w6: J1.39@2235,3190 2235,3200 2315,3280 2360,3280 2405,3325 2560,3325 2600,3365 R1_F15.1@2687.5,3365
INP16: J1.26 R1_F16.1 | length 450
  Top Layer w6: J1.26@2335,3325 2335,3350 2400,3415 2455,3415 2490,3380 2570,3380 2645,3455 R1_F16.1@2687.5,3455
INP17: J1.11 R1_F17.1 | length 368.9
  Bottom Layer w6: J1.11@2435,3370 2520,3370 2545,3395 2545,3470 2620,3545 R1_F17.1@2687.5,3545
INP18: J1.41 R1_F18.1 | length 568.1
  Top Layer w6: J1.41@2235,3370 2235,3380 2315,3460 2365,3460 2410,3505 2505,3505 2635,3635 R1_F18.1@2687.5,3635
INP19: J1.28 R1_F19.1 | length 505.8
  Bottom Layer w6: J1.28@2335,3505 2335,3530 2400,3595 2450,3595 2485,3560 2516.67,3560 2630,3673.33 2630,3705 2650,3725 R1_F19.1@2687.5,3725
INP20: J1.13 R1_F20.1 | length 476.5
  Top Layer w6: J1.13@2435,3550 2525,3550 2545,3570 2545,3705 2560,3720 2560,3780 2595,3815 R1_F20.1@2687.5,3815
INP21: J1.43 R1_F21.1 | length 657.8
  Bottom Layer w6: J1.43@2230,3570 2245,3570 2315,3640 2360,3640 2405,3685 2485,3685 2530,3730 2530,3835 2600,3905 R1_F21.1@2687.5,3905
INP22: J1.30 R1_F22.1 | length 486.8
  Top Layer w6: J1.30@2335,3685 2335,3695 2635,3995 R1_F22.1@2687.5,3995
NetC1_F1_1: C1_F1.1 L4_F1.1 R4_F1.2 | length 367.5
  Top Layer w15: R4_F1.2@2750,2105 v1(2975,2105) L4_F1.1@3042.5,2105 L4_F1.1@3047.5,2105
  Bottom Layer w15: C1_F1.1@2905,2105 v1(2975,2105)
NetC1_F1_2: C1_F1.2 L3_F1.1 R1_F1.2 | length 356.3
  Bottom Layer w15: R1_F1.2@2750,2105 C1_F1.2@2842.5,2105 2842.5,2137.5 2855,2150 3005,2150 L3_F1.1@3050,2105
NetC1_F2_1: C1_F2.1 L4_F2.1 R4_F2.2 | length 367.5
  Top Layer w15: C1_F2.1@2905,2195 v1(2975,2195)
  Bottom Layer w15: R4_F2.2@2750,2195 v1(2975,2195) L4_F2.1@3042.5,2195 L4_F2.1@3047.5,2195
NetC1_F2_2: C1_F2.2 L3_F2.1 R1_F2.2 | length 356.3
  Top Layer w15: R1_F2.2@2750,2195 C1_F2.2@2842.5,2195 2842.5,2227.5 2855,2240 3005,2240 L3_F2.1@3050,2195
NetC1_F3_1: C1_F3.1 L4_F3.1 R4_F3.2 | length 367.5
  Top Layer w15: R4_F3.2@2750,2285 v1(2975,2285) L4_F3.1@3042.5,2285 L4_F3.1@3047.5,2285
  Bottom Layer w15: C1_F3.1@2905,2285 v1(2975,2285)
NetC1_F3_2: C1_F3.2 L3_F3.1 R1_F3.2 | length 356.3
  Bottom Layer w15: R1_F3.2@2750,2285 C1_F3.2@2842.5,2285 2842.5,2317.5 2855,2330 3005,2330 L3_F3.1@3050,2285
NetC1_F4_1: C1_F4.1 L4_F4.1 R4_F4.2 | length 367.5
  Top Layer w15: C1_F4.1@2905,2375 v1(2975,2375)
  Bottom Layer w15: R4_F4.2@2750,2375 v1(2975,2375) L4_F4.1@3042.5,2375 L4_F4.1@3047.5,2375
NetC1_F4_2: C1_F4.2 L3_F4.1 R1_F4.2 | length 356.3
  Top Layer w15: R1_F4.2@2750,2375 C1_F4.2@2842.5,2375 2842.5,2407.5 2855,2420 3005,2420 L3_F4.1@3050,2375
